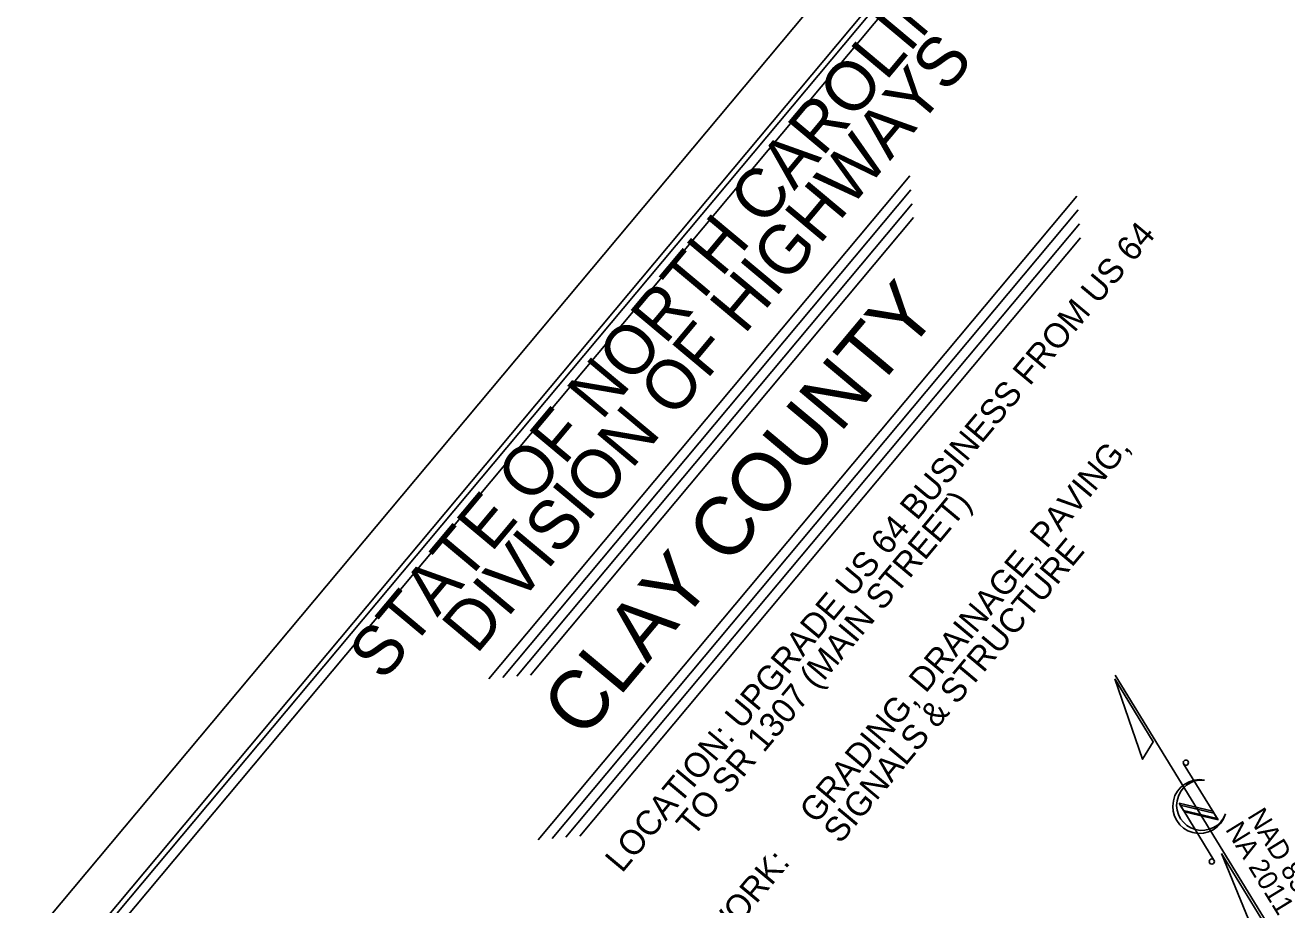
# Model space of a CAD drawing. Extents: x 555292 to 2368606, y 503623 to 1171444.
# Drawn here: x 2356645 to 2359845, y 1164538 to 1166770 of the extents above; entities that cross this region are included whole.
import ezdxf

# ---------------------------------------------------------------- set-up
doc = ezdxf.new("R2010")
doc.units = 0
for name, color, linetype in [('Sheet Cutting Line CELL', 7, 'Continuous'), ('Sheet Data Field CELL', 7, 'Continuous'), ('Sheet North Arrow CELL', 7, 'Continuous'), ('Sheet Plot Border Inside CELL', 7, 'Continuous'), ('Sheet Plot Border Outside CELL', 7, 'Continuous'), ('Sheet Title CELL', 7, 'Continuous')]:
    doc.layers.add(name, color=color, linetype=linetype)

msp = doc.modelspace()

# ---------------------------------------------------------------- linework, layer by layer
at = {"layer": 'Sheet Cutting Line CELL'}
msp.add_line((2355032.5, 1162506.7), (2360434.7, 1168965.2), dxfattribs=at)
at = {"layer": 'Sheet North Arrow CELL'}
for p, q in [((2359834.2, 1164427.7), (2359409.4, 1165120.3)), ((2359583.3, 1164895.3), (2359670.5, 1164753.1)), ((2359635.4, 1164854.3), (2359636.5, 1164854.3)), ((2359656.9, 1164775.3), (2359571.5, 1164795.8)), ((2359571.5, 1164795.8), (2359660.1, 1164651.3)), ((2359660.1, 1164770.1), (2359574.7, 1164790.5)), ((2359574.7, 1164790.5), (2359582.7, 1164777.5)), ((2359668.1, 1164757.1), (2359582.7, 1164777.5)), ((2359582.7, 1164777.5), (2359668.1, 1164757.1)), ((2359670.5, 1164753.1), (2359585.1, 1164773.6)), ((2359668.1, 1164757.1), (2359660.1, 1164770.1))]:
    msp.add_line(p, q, dxfattribs=at)
for points in [[(2359408.3, 1165111.3), (2359479.1, 1164907.1), (2359506.3, 1164951.4)], [(2359678.9, 1164668.2), (2359789.3, 1164400.2), (2359809.6, 1164455.1)]]:
    msp.add_lwpolyline(points, close=True, dxfattribs=at)
for centre in [(2359589, 1164898.6), (2359654.6, 1164647.6)]:
    msp.add_circle(centre, 6.63, dxfattribs=at)
for centre, radius, start, end in [((2359623.8, 1164787.2), 68.3, 79.3635, 343.9175), ((2359629.5, 1164790.6), 64, 84.6185, 340.1522)]:
    msp.add_arc(centre, radius, start, end, dxfattribs=at)
at = {"layer": 'Sheet Plot Border Inside CELL'}
msp.add_lwpolyline([(2359232.5, 1159130.5), (2364578.6, 1165521.9), (2360532, 1168906.6), (2355185.9, 1162515.2)], close=True, dxfattribs=at)
at = {"layer": 'Sheet Plot Border Outside CELL'}
msp.add_line((2355032.5, 1162506.7), (2360486, 1169026.6), dxfattribs=at)
at = {"layer": 'Sheet Title CELL'}
for p, q in [((2357821, 1165111.4), (2358888.4, 1166387.6)), ((2357856.1, 1165114.6), (2358891.5, 1166352.4)), ((2357945.9, 1164702.8), (2359312.5, 1166336.6)), ((2357891.4, 1165117.7), (2358894.6, 1166317.2)), ((2357981.1, 1164706), (2359315.6, 1166301.4)), ((2357926.6, 1165120.8), (2358897.8, 1166282)), ((2358016.3, 1164709.1), (2359318.7, 1166266.2)), ((2358051.5, 1164712.3), (2359321.9, 1166231))]:
    msp.add_line(p, q, dxfattribs=at)
for points in [[(2360469.6, 1168812.2), (2355721.7, 1163136)], [(2360472.7, 1168777), (2355917.5, 1163331)], [(2360472.7, 1168777), (2355917.5, 1163331)]]:
    msp.add_lwpolyline(points, dxfattribs=at)

# ---------------------------------------------------------------- texts
at = {"layer": 'Sheet Data Field CELL'}
for s, height, p in [('CLAY COUNTY', 148.588, (2358059.6, 1164953.8)), ('GRADING, DRAINAGE, PAVING,  ', 61.912, (2358651.3, 1164741)), ('SIGNALS & STRUCTURE', 61.912, (2358712, 1164690.3))]:
    msp.add_text(s, height=height, rotation=50.0895, dxfattribs=at).set_placement(p)
at = {"layer": 'Sheet North Arrow CELL'}
for s, p in [('NAD 83/', (2359743.7, 1164763.7)), ('NA 2011', (2359687.8, 1164729.4))]:
    msp.add_text(s, height=50, rotation=301.5234, dxfattribs=at).set_placement(p)
at = {"layer": 'Sheet Title CELL'}
for s, height, p in [('STATE OF NORTH CAROLINA', 125, (2357552.7, 1165102.1)), ('DIVISION OF HIGHWAYS', 125, (2357789.5, 1165171)), ('LOCATION: UPGRADE US 64 BUSINESS FROM US 64 ', 62.501, (2358158.7, 1164616.6)), ('        TO SR 1307 (MAIN STREET)', 62.501, (2358220, 1164565.4)), ('TYPE OF WORK:', 61.912, (2358165.5, 1164139.7))]:
    msp.add_text(s, height=height, rotation=50.0895, dxfattribs=at).set_placement(p)

doc.saveas('drawing.dxf')
